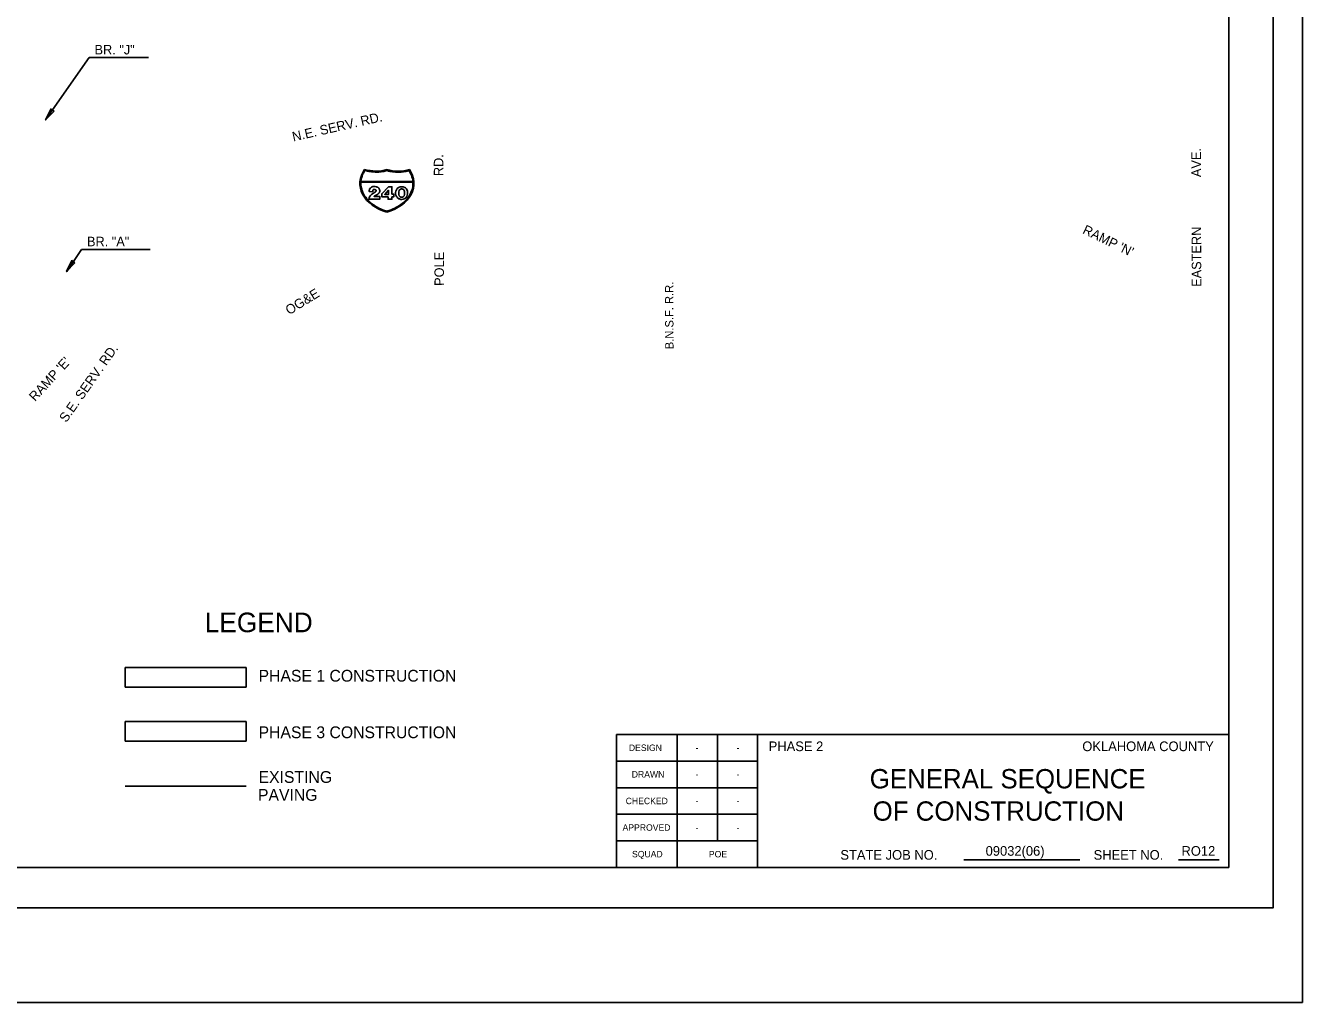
# Model space of a CAD drawing. Extents: x 2143531 to 2162022, y 139508 to 147626.
# Drawn here: x 2151304 to 2156666, y 139508 to 143608 of the extents above; entities that cross this region are included whole.
import ezdxf

# ---------------------------------------------------------------- set-up
doc = ezdxf.new("R2010")
doc.units = 0
for name, color, linetype in [('5', 7, 'Continuous'), ('7', 7, 'Continuous'), ('Default', 7, 'Continuous'), ('PR_Phasing_Bridge_5', 7, 'Continuous'), ('PR_Phasing_Pavement_1', 7, 'Continuous'), ('PR_Shading_Bridge_Phase_4', 7, 'Continuous'), ('PR_Shading_Pavement_Phase_1', 7, 'Continuous'), ('PR_Shading_Pavement_Phase_2', 7, 'Continuous'), ('SHT_Plot_Shape_Full', 7, 'Continuous'), ('SHT_Plot_Shape_Half', 7, 'Continuous'), ('SHT_Sheet_Border', 7, 'Continuous'), ('SHT_Standard_Sheet_Lines', 7, 'Continuous'), ('SHT_Standard_Sheet_Txt', 7, 'Continuous')]:
    doc.layers.add(name, color=color, linetype=linetype)

# ---------------------------------------------------------------- blocks, each defined once
blk = doc.blocks.new('ARROWHD')
at = {"layer": 'Default'}
blk.add_lwpolyline([(0.313, -0.054), (0.313, 0.052), (-0.005, -0.001)], close=True, dxfattribs=at)
blk = doc.blocks.new('i-240-shield')
at = {"layer": '7'}
blk.add_line((-18.14, 4.87), (18.76, 4.87), dxfattribs=at)
blk.add_line((-18.14, 4.87), (18.76, 4.87), dxfattribs=at)
for points in [[(-18.19, 4.17), (-18.21, 3.34), (-18.2, 2.74), (-18.15, 2.08), (-18.03, 1.02), (-17.84, 0.03), (-17.61, -0.87), (-17.3, -1.84), (-16.81, -3.04), (-16.3, -4.1), (-15.54, -5.4), (-14.75, -6.55), (-13.83, -7.71), (-12.99, -8.63), (-11.98, -9.62), (-11.44, -10.1), (-10.55, -10.85), (-9.63, -11.55), (-8.66, -12.22), (-7.48, -12.96), (-6.6, -13.47), (-5.36, -14.13), (-3.8, -14.86), (-2.74, -15.3), (-1.39, -15.81), (-0.45, -16.12), (0.31, -16.36), (1.08, -16.12), (2.01, -15.81), (3.36, -15.3), (4.42, -14.86), (5.98, -14.13), (7.23, -13.47), (8.11, -12.96), (9.29, -12.22), (10.26, -11.55), (11.17, -10.85), (12.07, -10.1), (12.61, -9.62), (13.62, -8.63), (14.45, -7.71), (15.37, -6.55), (16.17, -5.4), (16.92, -4.1), (17.44, -3.04), (17.92, -1.84), (18.23, -0.87), (18.46, 0.03), (18.65, 1.02), (18.78, 2.08), (18.82, 2.74), (18.84, 3.34), (18.81, 4.17), (-18.19, 4.17)], [(-12.32, -6.89), (-11.99, -6.14), (-11.64, -5.57), (-11.2, -5.11), (-10.65, -4.57), (-7.85, -2.75), (-7.38, -2.19), (-7.33, -2.12), (-7.33, -1.73), (-7.42, -1.37), (-7.47, -1.29), (-7.71, -1.1), (-8.22, -0.88), (-8.83, -0.88), (-9.35, -1.09), (-9.47, -1.2), (-9.72, -1.6), (-9.72, -2.53), (-12.22, -2.53), (-12.22, -1.73), (-12.11, -1.26), (-12, -0.88), (-11.76, -0.38), (-11.4, 0.02), (-10.73, 0.58), (-10.17, 0.86), (-9.71, 1.06), (-9.12, 1.15), (-8.13, 1.15), (-7.14, 0.97), (-6.57, 0.78), (-6.23, 0.58), (-5.77, 0.29), (-5.42, -0.1), (-5.19, -0.38), (-4.95, -0.78), (-4.84, -1.17), (-4.72, -1.65), (-4.72, -2.45), (-4.96, -2.97), (-5.19, -3.34), (-5.43, -3.64), (-6.08, -4.27), (-6.84, -4.83), (-8.63, -5.78), (-8.79, -5.89), (-4.72, -5.89), (-4.72, -7.91), (-12.49, -7.91), (-12.32, -6.89)], [(1.38, 1.07), (3.92, 1.07), (3.92, -4.15), (5.17, -4.15), (5.17, -6.17), (3.92, -6.17), (3.92, -7.91), (1.2, -7.91), (1.2, -6.17), (-3.37, -6.17), (-3.37, -3.99), (1.38, 1.07)], [(10.93, -7.91), (10.35, -7.91), (9.78, -7.81), (9.22, -7.63), (8.77, -7.44), (7.88, -6.88), (7.52, -6.48), (7.19, -6.01), (6.74, -5), (6.52, -4.06), (6.52, -3.04), (6.74, -2.04), (7.06, -1.04), (7.31, -0.63), (7.65, -0.24), (8.56, 0.5), (9.67, 0.88), (10.79, 1.07), (11.92, 0.88), (13.01, 0.51), (13.5, 0.2), (14.16, -0.53), (14.51, -1.02), (14.85, -1.85), (15.07, -2.86), (15.07, -3.89), (14.85, -4.91), (14.51, -5.82), (14.28, -6.21), (13.94, -6.59), (13.5, -7.06), (13.02, -7.36), (12.57, -7.54), (12.02, -7.72), (10.93, -7.91)], [(1.52, -4.47), (1.52, -1.51), (-1.19, -4.47), (1.52, -4.47)], [(10.17, -6.28), (10.69, -6.37), (10.9, -6.37), (11.42, -6.28), (11.94, -6.02), (12.36, -5.69), (12.57, -5.34), (12.77, -4.38), (12.88, -3.51), (12.77, -2.38), (12.57, -1.6), (12.36, -1.25), (12.15, -0.99), (12.04, -0.91), (11.73, -0.73), (11.31, -0.56), (11, -0.47), (10.69, -0.47), (10.17, -0.56), (9.96, -0.64), (9.65, -0.82), (9.23, -1.17), (9.02, -1.51), (8.81, -2.56), (8.71, -3.51), (8.81, -4.56), (9.13, -5.51), (9.44, -5.85), (9.65, -6.02), (10.17, -6.28)]]:
    blk.add_lwpolyline(points, dxfattribs=at)
for points in [[(-18.19, 4.17), (-18.21, 3.34), (-18.2, 2.74), (-18.15, 2.08), (-18.03, 1.02), (-17.84, 0.03), (-17.61, -0.87), (-17.3, -1.84), (-16.81, -3.04), (-16.3, -4.1), (-15.54, -5.4), (-14.75, -6.55), (-13.83, -7.71), (-12.99, -8.63), (-11.98, -9.62), (-11.44, -10.1), (-10.55, -10.85), (-9.63, -11.55), (-8.66, -12.22), (-7.48, -12.96), (-6.6, -13.47), (-5.36, -14.13), (-3.8, -14.86), (-2.74, -15.3), (-1.39, -15.81), (-0.45, -16.12), (0.31, -16.36), (1.08, -16.12), (2.01, -15.81), (3.36, -15.3), (4.42, -14.86), (5.98, -14.13), (7.23, -13.47), (8.11, -12.96), (9.29, -12.22), (10.26, -11.55), (11.17, -10.85), (12.07, -10.1), (12.61, -9.62), (13.62, -8.63), (14.45, -7.71), (15.37, -6.55), (16.17, -5.4), (16.92, -4.1), (17.44, -3.04), (17.92, -1.84), (18.23, -0.87), (18.46, 0.03), (18.65, 1.02), (18.78, 2.08), (18.82, 2.74), (18.84, 3.34), (18.81, 4.17)], [(-12.32, -6.89), (-11.99, -6.14), (-11.64, -5.57), (-11.2, -5.11), (-10.65, -4.57), (-7.85, -2.75), (-7.38, -2.19), (-7.33, -2.12), (-7.33, -1.73), (-7.42, -1.37), (-7.47, -1.29), (-7.71, -1.1), (-8.22, -0.88), (-8.83, -0.88), (-9.35, -1.09), (-9.47, -1.2), (-9.72, -1.6), (-9.72, -2.53), (-12.22, -2.53), (-12.22, -1.73), (-12.11, -1.26), (-12, -0.88), (-11.76, -0.38), (-11.4, 0.02), (-10.73, 0.58), (-10.17, 0.86), (-9.71, 1.06), (-9.12, 1.15), (-8.13, 1.15), (-7.14, 0.97), (-6.57, 0.78), (-6.23, 0.58), (-5.77, 0.29), (-5.42, -0.1), (-5.19, -0.38), (-4.95, -0.78), (-4.84, -1.17), (-4.72, -1.65), (-4.72, -2.45), (-4.96, -2.97), (-5.19, -3.34), (-5.43, -3.64), (-6.08, -4.27), (-6.84, -4.83), (-8.63, -5.78), (-8.79, -5.89), (-4.72, -5.89), (-4.72, -7.91), (-12.49, -7.91)], [(1.38, 1.07), (3.92, 1.07), (3.92, -4.15), (5.17, -4.15), (5.17, -6.17), (3.92, -6.17), (3.92, -7.91), (1.2, -7.91), (1.2, -6.17), (-3.37, -6.17), (-3.37, -3.99)], [(10.93, -7.91), (10.35, -7.91), (9.78, -7.81), (9.22, -7.63), (8.77, -7.44), (7.88, -6.88), (7.52, -6.48), (7.19, -6.01), (6.74, -5), (6.52, -4.06), (6.52, -3.04), (6.74, -2.04), (7.06, -1.04), (7.31, -0.63), (7.65, -0.24), (8.56, 0.5), (9.67, 0.88), (10.79, 1.07), (11.92, 0.88), (13.01, 0.51), (13.5, 0.2), (14.16, -0.53), (14.51, -1.02), (14.85, -1.85), (15.07, -2.86), (15.07, -3.89), (14.85, -4.91), (14.51, -5.82), (14.28, -6.21), (13.94, -6.59), (13.5, -7.06), (13.02, -7.36), (12.57, -7.54), (12.02, -7.72)], [(1.52, -1.51), (1.52, -4.47), (-1.19, -4.47)], [(9.44, -5.85), (9.13, -5.51), (9.13, -5.51), (8.81, -4.56), (8.71, -3.51), (8.81, -2.56), (9.02, -1.51), (9.23, -1.17), (9.65, -0.82), (9.96, -0.64), (10.17, -0.56), (10.69, -0.47), (11, -0.47), (11.31, -0.56), (11.73, -0.73), (12.04, -0.91), (12.15, -0.99), (12.36, -1.25), (12.57, -1.6), (12.77, -2.38), (12.88, -3.51), (12.77, -4.38), (12.57, -5.34), (12.36, -5.69), (11.94, -6.02), (11.42, -6.28), (10.9, -6.37), (10.69, -6.37), (10.17, -6.28), (9.65, -6.02)]]:
    blk.add_lwpolyline(points, close=True, dxfattribs=at)
for centre, major_axis, start_param, end_param in [((12.1, 3.38), (31.01, 0), 2.678593, 4.322471), ((-7.55, 27.2), (-21.16, 0), 1.177968, 1.951302), ((-11.47, 3.38), (-31.01, 0), 1.960714, 3.604592), ((8.17, 27.2), (21.16, 0), 4.331883, 5.105218)]:
    blk.add_ellipse(centre, major_axis=major_axis, ratio=0.713476, start_param=start_param, end_param=end_param, dxfattribs=at)
for points in [[(-15.35, 12.45), (-16.31, 11), (-17.04, 9.48), (-17.83, 6.92), (-18.03, 5.9), (-18.14, 4.87)], [(-15.35, 12.45), (-16.31, 11), (-17.04, 9.48), (-17.83, 6.92), (-18.03, 5.9), (-18.14, 4.87)], [(-15.35, 12.45), (-13.8, 12.02), (-12.19, 11.72), (-6.9, 11.19), (-3.13, 11.51), (0.31, 12.46)], [(0.31, 12.46), (-3.13, 11.51), (-6.9, 11.19), (-12.19, 11.72), (-13.8, 12.02), (-15.35, 12.45)], [(0.31, 12.46), (1.96, 12.01), (3.68, 11.69), (8.98, 11.21), (12.63, 11.53), (15.98, 12.45)], [(15.98, 12.45), (12.63, 11.53), (8.98, 11.21), (3.68, 11.69), (1.96, 12.01), (0.31, 12.46)], [(18.76, 4.87), (18.67, 5.78), (18.5, 6.68), (17.77, 9.25), (17.01, 10.89), (15.98, 12.45)], [(18.76, 4.87), (18.67, 5.78), (18.5, 6.68), (17.77, 9.25), (17.01, 10.89), (15.98, 12.45)]]:
    blk.add_open_spline(points, degree=3, dxfattribs=at)
at = {"layer": 'Default'}
for p, q in [((-12.12, -7.59), (-12.12, -7.59)), ((1.52, -4.47), (1.52, -4.47)), ((1.52, -7.59), (1.52, -7.59))]:
    blk.add_line(p, q, dxfattribs=at)

msp = doc.modelspace()

# ---------------------------------------------------------------- linework, layer by layer
at = {"layer": '5'}
for p, q in [((2151388.7, 143212.6), (2151570.8, 143473.2)), ((2151821.1, 143473.2), (2151570.8, 143473.2)), ((2151477.1, 142576.3), (2151539.1, 142667.8)), ((2151827.5, 142667.8), (2151539.1, 142667.8))]:
    msp.add_line(p, q, dxfattribs=at)
at = {"layer": '7'}
msp.add_lwpolyline([(2152712.3, 142950.5), (2152712.6, 142954.6), (2152930.5, 142953.7), (2152930.8, 142949.6)], close=True, dxfattribs=at)
at = {"layer": 'PR_Phasing_Bridge_5'}
msp.add_line((2151722.6, 140415), (2152230.2, 140415), dxfattribs=at)
at = {"layer": 'PR_Phasing_Pavement_1'}
for p, q in [((2152230.2, 140686.4), (2151722.6, 140686.4)), ((2151722.6, 140686.4), (2151722.6, 140604.9)), ((2152230.2, 140686.4), (2151722.6, 140686.4)), ((2151722.6, 140686.4), (2151722.6, 140604.9)), ((2152230.2, 140686.4), (2151722.6, 140686.4)), ((2151722.6, 140686.4), (2151722.6, 140604.9)), ((2152230.2, 140604.9), (2152230.2, 140686.4)), ((2152230.2, 140604.9), (2152230.2, 140686.4)), ((2152230.2, 140604.9), (2152230.2, 140686.4)), ((2151722.6, 140604.9), (2152230.2, 140604.9)), ((2151722.6, 140604.9), (2152230.2, 140604.9)), ((2151722.6, 140604.9), (2152230.2, 140604.9))]:
    msp.add_line(p, q, dxfattribs=at)
at = {"layer": 'PR_Shading_Pavement_Phase_1'}
for p, q in [((2151722.6, 140912.8), (2152230.2, 140912.8)), ((2151722.6, 140912.8), (2151722.6, 140831.4)), ((2152230.2, 140912.8), (2152230.2, 140831.4)), ((2151722.6, 140831.4), (2152230.2, 140831.4)), ((2151722.6, 140686.4), (2152230.2, 140686.4)), ((2151722.6, 140686.4), (2151722.6, 140604.9)), ((2151722.6, 140686.4), (2152230.2, 140686.4)), ((2152230.2, 140604.9), (2152230.2, 140686.4)), ((2151722.6, 140604.9), (2152230.2, 140604.9)), ((2151722.6, 140604.9), (2152230.2, 140604.9))]:
    msp.add_line(p, q, dxfattribs=at)
at = {"layer": 'PR_Shading_Pavement_Phase_2'}
for p, q in [((2152230.2, 140912.8), (2151722.6, 140912.8)), ((2151722.6, 140912.8), (2151722.6, 140831.4)), ((2152230.2, 140831.4), (2152230.2, 140912.8)), ((2151722.6, 140831.4), (2152230.2, 140831.4))]:
    msp.add_line(p, q, dxfattribs=at)
at = {"layer": 'SHT_Plot_Shape_Full'}
msp.add_lwpolyline([(2144487.6, 147626.1), (2156665.5, 147626.1), (2156665.5, 139507.5), (2144487.6, 139507.5)], close=True, dxfattribs=at)
at = {"layer": 'SHT_Plot_Shape_Half'}
msp.add_lwpolyline([(2145041.6, 147347.1), (2156542.9, 147347.1), (2156542.9, 139905), (2145041.6, 139905)], close=True, dxfattribs=at)
at = {"layer": 'SHT_Sheet_Border'}
for p, q in [((2153786, 140074.1), (2153786, 140632.3)), ((2153786, 140632.3), (2156356.9, 140632.3)), ((2154377.9, 140074.1), (2154377.9, 140632.6))]:
    msp.add_line(p, q, dxfattribs=at)
msp.add_lwpolyline([(2156356.9, 140074.1), (2145701.2, 140074.1), (2145701.2, 147177.9), (2156356.9, 147177.9)], close=True, dxfattribs=at)
at = {"layer": 'SHT_Standard_Sheet_Lines'}
for p, q in [((2154039.7, 140074.1), (2154039.7, 140632.6)), ((2154208.8, 140185.8), (2154208.8, 140632.6)), ((2155244.2, 140106.7), (2155731.4, 140106.7)), ((2156145.6, 140106.7), (2156315.6, 140106.7))]:
    msp.add_line(p, q, dxfattribs=at)
for points in [[(2154377.9, 140520.7), (2153786, 140520.7)], [(2154377.9, 140409), (2153786, 140409)], [(2154377.9, 140297.4), (2153786, 140297.4)], [(2154377.9, 140185.8), (2153786, 140185.8)]]:
    msp.add_lwpolyline(points, dxfattribs=at)

# ---------------------------------------------------------------- block references
at = {"layer": '5'}
for p, xscale, yscale, rotation in [((2151388.7, 143212.6), 157.48000000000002, 157.48, 55.04814174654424), ((2151477.1, 142576.3), 157.48, 157.47999999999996, 55.88201680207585)]:
    msp.add_blockref('ARROWHD', p, dxfattribs=dict(at, xscale=xscale, yscale=yscale, rotation=rotation))
at = {"layer": '7', "xscale": 5.905500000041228, "yscale": 5.905500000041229, "rotation": -0.2304623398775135}
msp.add_blockref('i-240-shield', (2152819.6, 142925.4), dxfattribs=at)

# ---------------------------------------------------------------- texts
at = {"layer": 'PR_Shading_Bridge_Phase_4'}
for s, height, rotation, p in [('BR. "J"', 40, 360, (2151593.9, 143486.8)), ('N.E. SERV. RD.', 40, 12.8297, (2152428.7, 143121.2)), ('RD.', 40, 90.1579, (2153058.4, 142976.1)), ('EASTERN              AVE.', 40, 90.1579, (2156240.8, 142511.2)), ("RAMP 'N'", 40, 333.9781, (2155739.1, 142737.2)), ('POLE', 40, 90.1579, (2153061.2, 142515.3)), ('OG&E', 40, 31.6564, (2152410.9, 142391.9)), ('B.N.S.F. R.R.', 35, 90.1579, (2154024.9, 142249.4)), ('S.E. SERV. RD.', 40, 54.9105, (2151475.2, 141939.2)), ("RAMP 'E'", 40, 47.4663, (2151344.2, 142027.8)), ('LEGEND', 82.42, 360, (2152056.6, 141061.5)), ('PHASE 1 CONSTRUCTION', 49.455, 360, (2152282.6, 140854.1)), ('PHASE 3 CONSTRUCTION', 49.455, 360, (2152282.6, 140616.8)), ('EXISTING', 49.45, 360, (2152282.6, 140429.1)), ('PAVING', 49.45, 360, (2152280.2, 140354))]:
    msp.add_text(s, height=height, rotation=rotation, dxfattribs=at).set_placement(p)
msp.add_text('BR. "A"', height=40, dxfattribs=at).set_placement((2151562.2, 142681.5))
at = {"layer": 'SHT_Standard_Sheet_Txt'}
for s, height, p in [('DESIGN', 27.06, (2153837.4, 140563.1)), ('-', 27.1, (2154117.6, 140563.1)), ('-', 27.1, (2154289.6, 140563.1)), ('OKLAHOMA COUNTY', 40.596, (2155741.2, 140562.4)), ('DRAWN', 27.06, (2153849.5, 140451.5)), ('GENERAL SEQUENCE', 81.186, (2154848.5, 140406)), ('-', 27.1, (2154117.6, 140451.4)), ('-', 27.1, (2154289.6, 140451.4)), ('CHECKED', 27.06, (2153824.1, 140339.8)), ('-', 27.1, (2154117.6, 140339.7)), ('-', 27.1, (2154289.6, 140339.7)), ('OF CONSTRUCTION', 81.186, (2154860.8, 140270.4)), ('APPROVED', 27.06, (2153810.9, 140228.2)), ('-', 27.1, (2154117.6, 140228)), ('-', 27.1, (2154289.6, 140228)), ('STATE JOB NO.', 40.593, (2154725.4, 140106.7)), ('09032(06)', 40.59, (2155335.3, 140123.3)), ('SHEET NO. ', 40.59, (2155788.7, 140106.7)), ('RO12', 40.59, (2156157.6, 140123.3)), ('SQUAD', 27.06, (2153850.7, 140116.6)), ('POE', 27.06, (2154173.3, 140116.4))]:
    msp.add_text(s, height=height, dxfattribs=at).set_placement(p)
msp.add_text('PHASE 2', height=40.6, rotation=0, dxfattribs=at).set_placement((2154424.4, 140562.4))

doc.saveas('drawing.dxf')
